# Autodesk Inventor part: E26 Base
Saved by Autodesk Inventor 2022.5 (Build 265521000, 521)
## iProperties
Created: 2024-07
Part Number: E26 Base
Material: Generic
Document SubType Name: Modeling
Designer: AdminForWorker
Density: 1 g/cm^3
Appearance: Default
Title: E26 Base
Author: AdminForWorker
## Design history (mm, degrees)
feature "E26 Base"
body "Solid1"
